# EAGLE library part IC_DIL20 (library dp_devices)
Universal 20pins IC
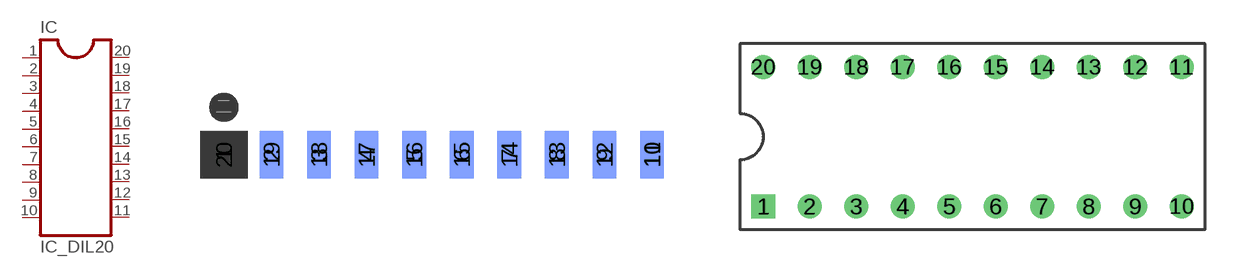
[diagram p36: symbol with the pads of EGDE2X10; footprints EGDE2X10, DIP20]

Designator prefix IC

## IC_DIL20-EDGE  [EGDE2X10]
1  1
2  2
3  3
4  4
5  5
6  6
7  7
8  8
9  9
10  10
11  11
12  12
13  13
14  14
15  15
16  16
17  17
18  18
19  19
20  20

## IC_DIL20-PTH  [DIP20]
Pads as for EGDE2X10

## Footprint EGDE2X10 (pad centres in mm)
smd 1.27 x 2.54: 1 -11.43,0; 2 -8.89,0; 3 -6.35,0; 4 -3.81,0; 5 -1.27,0; 6 1.27,0; 7 3.81,0; 8 6.35,0; 9 8.89,0; 10 11.43,0
smd 1.27 x 2.54 bottom: 11 11.43,0; 12 8.89,0; 13 6.35,0; 14 3.81,0; 15 1.27,0; 16 -1.27,0; 17 -3.81,0; 18 -6.35,0; 19 -8.89,0; 20 -11.43,0

## Footprint DIP20 (pad centres in mm)
drill 0.8 square: 1 -11.43,-3.81
drill 0.8 round: 2 -8.89,-3.81; 3 -6.35,-3.81; 4 -3.81,-3.81; 5 -1.27,-3.81; 6 1.27,-3.81; 7 3.81,-3.81; 8 6.35,-3.81; 9 8.89,-3.81; 10 11.43,-3.81; 11 11.43,3.81; 12 8.89,3.81; 13 6.35,3.81; 14 3.81,3.81; 15 1.27,3.81; 16 -1.27,3.81; 17 -3.81,3.81; 18 -6.35,3.81; 19 -8.89,3.81; 20 -11.43,3.81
